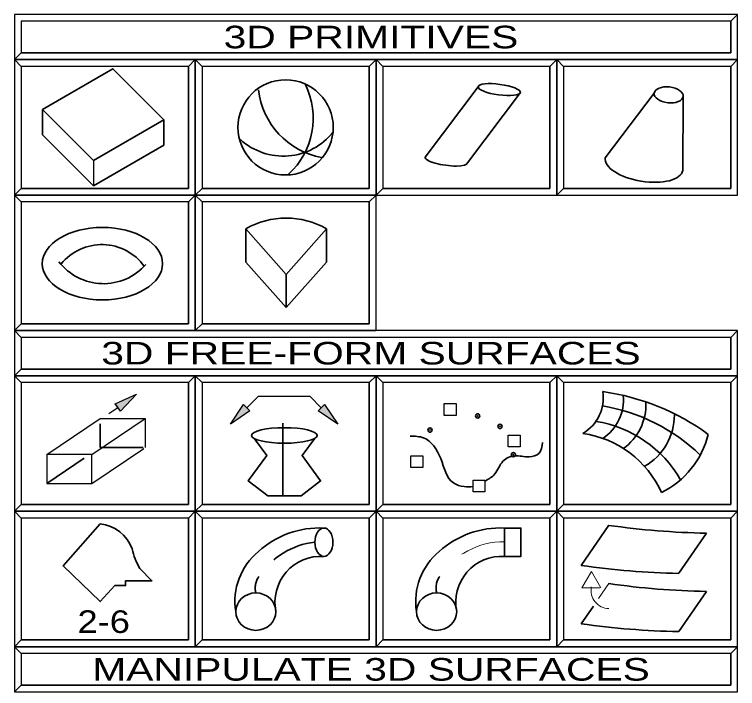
# Model space of a CAD drawing. Extents: x 95906.9 to 95918.9, y 90964.8 to 90972.9.
# Drawn here: x 95914.53 to 95916.13, y 90968.169 to 90969.662 of the extents above; entities that cross this region are included whole.
import ezdxf
from ezdxf.enums import TextEntityAlignment as Align

# ---------------------------------------------------------------- set-up
doc = ezdxf.new("R2010")
doc.units = 0
doc.header["$LTSCALE"] = 0.019
doc.header["$PDMODE"] = 32
doc.header["$PDSIZE"] = 0.0095
doc.linetypes.add('MEDIUM_DASHED', pattern=[4.5, 3, -1.5])
for name, color, linetype, lineweight in [('1', 7, 'Continuous', 25), ('11', 7, 'Continuous', 25), ('17', 7, 'Continuous', 25), ('18', 7, 'Continuous', 25), ('2', 7, 'Continuous', 13), ('3', 7, 'Continuous', 25), ('4', 7, 'Continuous', 35), ('6', 7, 'Continuous', 35), ('7', 7, 'Continuous', 35)]:
    doc.layers.add(name, color=color, linetype=linetype, lineweight=lineweight)

msp = doc.modelspace()

# ---------------------------------------------------------------- hatches: boundary and pattern name
at = {"layer": '6'}
for points in [[(95914.7526, 90968.7998), (95914.8002, 90968.8212), (95914.7644, 90968.7832)], [(95915.0509, 90968.7838), (95915.0075, 90968.7548), (95915.0365, 90968.7982)], [(95915.216, 90968.7982), (95915.245, 90968.7548), (95915.2016, 90968.7838)]]:
    msp.add_hatch(color=256, dxfattribs=at).paths.add_polyline_path(points)

# ---------------------------------------------------------------- linework, layer by layer
at = {"layer": '1'}
for points in [[(95914.5298, 90969.5617), (95916.1298, 90969.5617), (95916.1298, 90969.6617), (95914.5298, 90969.6617)], [(95914.5298, 90969.2617), (95914.9298, 90969.2617), (95914.9298, 90969.5617), (95914.5298, 90969.5617)], [(95914.9298, 90969.2617), (95915.3298, 90969.2617), (95915.3298, 90969.5617), (95914.9298, 90969.5617)], [(95915.3298, 90969.2617), (95915.7298, 90969.2617), (95915.7298, 90969.5617), (95915.3298, 90969.5617)], [(95915.7298, 90969.2617), (95916.1298, 90969.2617), (95916.1298, 90969.5617), (95915.7298, 90969.5617)], [(95914.5298, 90968.9617), (95914.9298, 90968.9617), (95914.9298, 90969.2617), (95914.5298, 90969.2617)], [(95914.9298, 90968.9617), (95915.3298, 90968.9617), (95915.3298, 90969.2617), (95914.9298, 90969.2617)], [(95914.5298, 90968.8617), (95916.1298, 90968.8617), (95916.1298, 90968.9617), (95914.5298, 90968.9617)], [(95914.5298, 90968.5617), (95914.9298, 90968.5617), (95914.9298, 90968.8617), (95914.5298, 90968.8617)], [(95914.9298, 90968.5617), (95915.3298, 90968.5617), (95915.3298, 90968.8617), (95914.9298, 90968.8617)], [(95915.3298, 90968.5617), (95915.7298, 90968.5617), (95915.7298, 90968.8617), (95915.3298, 90968.8617)], [(95915.7298, 90968.5617), (95916.1298, 90968.5617), (95916.1298, 90968.8617), (95915.7298, 90968.8617)], [(95914.5298, 90968.2617), (95914.9298, 90968.2617), (95914.9298, 90968.5617), (95914.5298, 90968.5617)], [(95914.9298, 90968.2617), (95915.3298, 90968.2617), (95915.3298, 90968.5617), (95914.9298, 90968.5617)], [(95915.3298, 90968.2617), (95915.7298, 90968.2617), (95915.7298, 90968.5617), (95915.3298, 90968.5617)], [(95915.7298, 90968.2617), (95916.1298, 90968.2617), (95916.1298, 90968.5617), (95915.7298, 90968.5617)], [(95914.5298, 90968.1617), (95916.1298, 90968.1617), (95916.1298, 90968.2617), (95914.5298, 90968.2617)]]:
    msp.add_lwpolyline(points, close=True, dxfattribs=at)
at = {"layer": '11'}
for points in [[(95914.5448, 90969.2767), (95914.9148, 90969.2767), (95914.9148, 90969.5467), (95914.5448, 90969.5467)], [(95914.9448, 90969.2767), (95915.3148, 90969.2767), (95915.3148, 90969.5467), (95914.9448, 90969.5467)], [(95915.3448, 90969.2767), (95915.7148, 90969.2767), (95915.7148, 90969.5467), (95915.3448, 90969.5467)], [(95915.7448, 90969.2767), (95916.1148, 90969.2767), (95916.1148, 90969.5467), (95915.7448, 90969.5467)], [(95914.5448, 90968.9767), (95914.9148, 90968.9767), (95914.9148, 90969.2467), (95914.5448, 90969.2467)], [(95914.9448, 90968.9767), (95915.3148, 90968.9767), (95915.3148, 90969.2467), (95914.9448, 90969.2467)], [(95914.5448, 90968.5767), (95914.9148, 90968.5767), (95914.9148, 90968.8467), (95914.5448, 90968.8467)], [(95914.9448, 90968.5767), (95915.3148, 90968.5767), (95915.3148, 90968.8467), (95914.9448, 90968.8467)], [(95915.3448, 90968.5767), (95915.7148, 90968.5767), (95915.7148, 90968.8467), (95915.3448, 90968.8467)], [(95915.7448, 90968.5767), (95916.1148, 90968.5767), (95916.1148, 90968.8467), (95915.7448, 90968.8467)], [(95914.5448, 90968.2767), (95914.9148, 90968.2767), (95914.9148, 90968.5467), (95914.5448, 90968.5467)], [(95914.9448, 90968.2767), (95915.3148, 90968.2767), (95915.3148, 90968.5467), (95914.9448, 90968.5467)], [(95915.3448, 90968.2767), (95915.7148, 90968.2767), (95915.7148, 90968.5467), (95915.3448, 90968.5467)], [(95915.7448, 90968.2767), (95916.1148, 90968.2767), (95916.1148, 90968.5467), (95915.7448, 90968.5467)]]:
    msp.add_lwpolyline(points, close=True, dxfattribs=at)
at = {"layer": '17'}
for points in [[(95914.5448, 90969.5767), (95916.1148, 90969.5767), (95916.1148, 90969.6467), (95914.5448, 90969.6467)], [(95914.5448, 90968.8767), (95916.1148, 90968.8767), (95916.1148, 90968.9467), (95914.5448, 90968.9467)]]:
    msp.add_lwpolyline(points, close=True, dxfattribs=at)
at = {"layer": '18'}
msp.add_lwpolyline([(95914.5448, 90968.1767), (95916.1148, 90968.1767), (95916.1148, 90968.2467), (95914.5448, 90968.2467)], close=True, dxfattribs=at)
at = {"layer": '2'}
for points in [[(95914.5298, 90969.6617), (95914.5298, 90969.5617), (95914.5448, 90969.5767), (95914.5448, 90969.6467), (95916.1148, 90969.6467), (95916.1298, 90969.6617)], [(95914.5298, 90969.5617), (95914.5298, 90969.2617), (95914.5448, 90969.2767), (95914.5448, 90969.5467), (95914.9148, 90969.5467), (95914.9298, 90969.5617)], [(95914.9298, 90969.5617), (95914.9298, 90969.2617), (95914.9448, 90969.2767), (95914.9448, 90969.5467), (95915.3148, 90969.5467), (95915.3298, 90969.5617)], [(95915.3298, 90969.5617), (95915.3298, 90969.2617), (95915.3448, 90969.2767), (95915.3448, 90969.5467), (95915.7148, 90969.5467), (95915.7298, 90969.5617)], [(95915.7298, 90969.5617), (95915.7298, 90969.2617), (95915.7448, 90969.2767), (95915.7448, 90969.5467), (95916.1148, 90969.5467), (95916.1298, 90969.5617)], [(95914.5298, 90969.2617), (95914.5298, 90968.9617), (95914.5448, 90968.9767), (95914.5448, 90969.2467), (95914.9148, 90969.2467), (95914.9298, 90969.2617)], [(95914.9298, 90969.2617), (95914.9298, 90968.9617), (95914.9448, 90968.9767), (95914.9448, 90969.2467), (95915.3148, 90969.2467), (95915.3298, 90969.2617)], [(95914.5298, 90968.9617), (95914.5298, 90968.8617), (95914.5448, 90968.8767), (95914.5448, 90968.9467), (95916.1148, 90968.9467), (95916.1298, 90968.9617)], [(95914.5298, 90968.8617), (95914.5298, 90968.5617), (95914.5448, 90968.5767), (95914.5448, 90968.8467), (95914.9148, 90968.8467), (95914.9298, 90968.8617)], [(95914.9298, 90968.8617), (95914.9298, 90968.5617), (95914.9448, 90968.5767), (95914.9448, 90968.8467), (95915.3148, 90968.8467), (95915.3298, 90968.8617)], [(95915.3298, 90968.8617), (95915.3298, 90968.5617), (95915.3448, 90968.5767), (95915.3448, 90968.8467), (95915.7148, 90968.8467), (95915.7298, 90968.8617)], [(95915.7298, 90968.8617), (95915.7298, 90968.5617), (95915.7448, 90968.5767), (95915.7448, 90968.8467), (95916.1148, 90968.8467), (95916.1298, 90968.8617)], [(95914.5298, 90968.5617), (95914.5298, 90968.2617), (95914.5448, 90968.2767), (95914.5448, 90968.5467), (95914.9148, 90968.5467), (95914.9298, 90968.5617)], [(95914.9298, 90968.5617), (95914.9298, 90968.2617), (95914.9448, 90968.2767), (95914.9448, 90968.5467), (95915.3148, 90968.5467), (95915.3298, 90968.5617)], [(95915.3298, 90968.5617), (95915.3298, 90968.2617), (95915.3448, 90968.2767), (95915.3448, 90968.5467), (95915.7148, 90968.5467), (95915.7298, 90968.5617)], [(95915.7298, 90968.5617), (95915.7298, 90968.2617), (95915.7448, 90968.2767), (95915.7448, 90968.5467), (95916.1148, 90968.5467), (95916.1298, 90968.5617)], [(95914.5298, 90968.2617), (95914.5298, 90968.1617), (95914.5448, 90968.1767), (95914.5448, 90968.2467), (95916.1148, 90968.2467), (95916.1298, 90968.2617)]]:
    msp.add_lwpolyline(points, close=True, dxfattribs=at)
at = {"layer": '3'}
for points in [[(95914.5298, 90969.5617), (95916.1298, 90969.5617), (95916.1298, 90969.6617), (95916.1148, 90969.6467), (95916.1148, 90969.5767), (95914.5448, 90969.5767)], [(95914.5298, 90969.2617), (95914.9298, 90969.2617), (95914.9298, 90969.5617), (95914.9148, 90969.5467), (95914.9148, 90969.2767), (95914.5448, 90969.2767)], [(95914.9298, 90969.2617), (95915.3298, 90969.2617), (95915.3298, 90969.5617), (95915.3148, 90969.5467), (95915.3148, 90969.2767), (95914.9448, 90969.2767)], [(95915.3298, 90969.2617), (95915.7298, 90969.2617), (95915.7298, 90969.5617), (95915.7148, 90969.5467), (95915.7148, 90969.2767), (95915.3448, 90969.2767)], [(95915.7298, 90969.2617), (95916.1298, 90969.2617), (95916.1298, 90969.5617), (95916.1148, 90969.5467), (95916.1148, 90969.2767), (95915.7448, 90969.2767)], [(95914.5298, 90968.9617), (95914.9298, 90968.9617), (95914.9298, 90969.2617), (95914.9148, 90969.2467), (95914.9148, 90968.9767), (95914.5448, 90968.9767)], [(95914.9298, 90968.9617), (95915.3298, 90968.9617), (95915.3298, 90969.2617), (95915.3148, 90969.2467), (95915.3148, 90968.9767), (95914.9448, 90968.9767)], [(95914.5298, 90968.8617), (95916.1298, 90968.8617), (95916.1298, 90968.9617), (95916.1148, 90968.9467), (95916.1148, 90968.8767), (95914.5448, 90968.8767)], [(95914.5298, 90968.5617), (95914.9298, 90968.5617), (95914.9298, 90968.8617), (95914.9148, 90968.8467), (95914.9148, 90968.5767), (95914.5448, 90968.5767)], [(95914.9298, 90968.5617), (95915.3298, 90968.5617), (95915.3298, 90968.8617), (95915.3148, 90968.8467), (95915.3148, 90968.5767), (95914.9448, 90968.5767)], [(95915.3298, 90968.5617), (95915.7298, 90968.5617), (95915.7298, 90968.8617), (95915.7148, 90968.8467), (95915.7148, 90968.5767), (95915.3448, 90968.5767)], [(95915.7298, 90968.5617), (95916.1298, 90968.5617), (95916.1298, 90968.8617), (95916.1148, 90968.8467), (95916.1148, 90968.5767), (95915.7448, 90968.5767)], [(95914.5298, 90968.2617), (95914.9298, 90968.2617), (95914.9298, 90968.5617), (95914.9148, 90968.5467), (95914.9148, 90968.2767), (95914.5448, 90968.2767)], [(95914.9298, 90968.2617), (95915.3298, 90968.2617), (95915.3298, 90968.5617), (95915.3148, 90968.5467), (95915.3148, 90968.2767), (95914.9448, 90968.2767)], [(95915.3298, 90968.2617), (95915.7298, 90968.2617), (95915.7298, 90968.5617), (95915.7148, 90968.5467), (95915.7148, 90968.2767), (95915.3448, 90968.2767)], [(95915.7298, 90968.2617), (95916.1298, 90968.2617), (95916.1298, 90968.5617), (95916.1148, 90968.5467), (95916.1148, 90968.2767), (95915.7448, 90968.2767)], [(95914.5298, 90968.1617), (95916.1298, 90968.1617), (95916.1298, 90968.2617), (95916.1148, 90968.2467), (95916.1148, 90968.1767), (95914.5448, 90968.1767)]]:
    msp.add_lwpolyline(points, close=True, dxfattribs=at)
at = {"layer": '4'}
for p, q in [((95914.5448, 90969.5467), (95914.5298, 90969.5617)), ((95914.9448, 90969.5467), (95914.9298, 90969.5617)), ((95915.3448, 90969.5467), (95915.3298, 90969.5617)), ((95915.7448, 90969.5467), (95915.7298, 90969.5617)), ((95914.5448, 90969.2467), (95914.5298, 90969.2617)), ((95914.9448, 90969.2467), (95914.9298, 90969.2617)), ((95914.5448, 90968.9467), (95914.5298, 90968.9617)), ((95914.5448, 90968.8467), (95914.5298, 90968.8617)), ((95914.9448, 90968.8467), (95914.9298, 90968.8617)), ((95915.3448, 90968.8467), (95915.3298, 90968.8617)), ((95915.7448, 90968.8467), (95915.7298, 90968.8617)), ((95914.5448, 90968.5467), (95914.5298, 90968.5617)), ((95914.9448, 90968.5467), (95914.9298, 90968.5617)), ((95915.3448, 90968.5467), (95915.3298, 90968.5617)), ((95915.7448, 90968.5467), (95915.7298, 90968.5617)), ((95914.5448, 90968.2467), (95914.5298, 90968.2617))]:
    msp.add_line(p, q, dxfattribs=at)
at = {"layer": '6'}
for p, q in [((95915.5558, 90969.5016), (95915.4387, 90969.3456)), ((95915.5323, 90969.3331), (95915.6494, 90969.4891)), ((95915.9453, 90969.4873), (95915.8371, 90969.3446)), ((95916.0096, 90969.48), (95916.0085, 90969.3164)), ((95914.5919, 90969.4516), (95914.7048, 90969.3387)), ((95914.5919, 90969.4516), (95914.5919, 90969.3953)), ((95914.7048, 90969.3387), (95914.8605, 90969.4286)), ((95914.7048, 90969.2824), (95914.5919, 90969.3953)), ((95914.7048, 90969.2824), (95914.8605, 90969.3723)), ((95915.1311, 90969.0863), (95915.0419, 90969.187)), ((95915.0419, 90969.1133), (95915.0419, 90969.187)), ((95915.2203, 90969.1133), (95915.2203, 90969.187)), ((95915.1311, 90969.0126), (95915.0419, 90969.1133)), ((95915.1311, 90969.0126), (95915.2203, 90969.1133)), ((95915.0687, 90968.816), (95915.0437, 90968.791)), ((95915.1838, 90968.816), (95915.2088, 90968.791)), ((95915.1235, 90968.7566), (95915.1235, 90968.5971)), ((95915.845, 90968.5306), (95915.784, 90968.4417)), ((95916.0608, 90968.5131), (95915.9998, 90968.4243)), ((95916.0608, 90968.3842), (95915.9998, 90968.2953)), ((95915.811, 90968.3518), (95915.784, 90968.3128))]:
    msp.add_line(p, q, dxfattribs=at)
at = {"layer": '6', "lineweight": 25}
for p, q in [((95914.7048, 90969.3387), (95914.7048, 90969.2824)), ((95915.1838, 90968.816), (95915.0687, 90968.816)), ((95914.7641, 90968.7834), (95914.7524, 90968.8001)), ((95914.7389, 90968.7782), (95914.7582, 90968.7918)), ((95914.6013, 90968.6877), (95914.7192, 90968.7672)), ((95914.7007, 90968.6877), (95914.8187, 90968.7673)), ((95914.7007, 90968.6233), (95914.8158, 90968.7009))]:
    msp.add_line(p, q, dxfattribs=at)
at = {"layer": '6', "linetype": 'MEDIUM_DASHED'}
msp.add_line((95914.6013, 90968.6233), (95914.6901, 90968.6832), dxfattribs=at)
at = {"layer": '6', "lineweight": 13}
for p, q in [((95915.6145, 90968.4618), (95915.6505, 90968.4618)), ((95915.845, 90968.4015), (95915.8224, 90968.3687)), ((95915.7854, 90968.3924), (95915.825, 90968.3924))]:
    msp.add_line(p, q, dxfattribs=at)
at = {"layer": '6'}
for points in [[(95914.5919, 90969.4516), (95914.7476, 90969.5415), (95914.8605, 90969.4286), (95914.8605, 90969.3723)], [(95915.1311, 90969.0126), (95915.1311, 90969.0863), (95915.2203, 90969.187)], [(95915.0609, 90968.7224), (95915.0882, 90968.6853), (95915.0473, 90968.6288), (95915.0902, 90968.5956), (95915.1644, 90968.5956)], [(95915.1937, 90968.7224), (95915.1664, 90968.6853), (95915.2073, 90968.6288), (95915.1644, 90968.5956)], [(95914.7195, 90968.5336), (95914.6379, 90968.4409), (95914.7195, 90968.3616), (95914.7516, 90968.397), (95914.7756, 90968.397), (95914.7756, 90968.4079), (95914.8341, 90968.4079), (95914.8073, 90968.4348)]]:
    msp.add_lwpolyline(points, dxfattribs=at)
at = {"layer": '6', "lineweight": 25}
for points in [[(95914.7526, 90968.7998), (95914.8002, 90968.8212), (95914.7644, 90968.7832)], [(95915.481, 90968.8), (95915.507, 90968.8), (95915.507, 90968.774), (95915.481, 90968.774)], [(95915.0509, 90968.7838), (95915.0075, 90968.7548), (95915.0365, 90968.7982)], [(95915.216, 90968.7982), (95915.245, 90968.7548), (95915.2016, 90968.7838)], [(95915.6226, 90968.7302), (95915.6486, 90968.7302), (95915.6486, 90968.7042), (95915.6226, 90968.7042)], [(95914.6013, 90968.6233), (95914.7007, 90968.6233), (95914.7007, 90968.6877), (95914.6013, 90968.6877)], [(95915.4071, 90968.6843), (95915.4331, 90968.6843), (95915.4331, 90968.6583), (95915.4071, 90968.6583)], [(95915.5448, 90968.6304), (95915.5708, 90968.6304), (95915.5708, 90968.6044), (95915.5448, 90968.6044)]]:
    msp.add_lwpolyline(points, close=True, dxfattribs=at)
msp.add_lwpolyline([(95914.7192, 90968.7672), (95914.8187, 90968.7672), (95914.8187, 90968.7028), (95914.8187, 90968.7028)], dxfattribs=at)
at = {"layer": '6', "linetype": 'MEDIUM_DASHED'}
msp.add_lwpolyline([(95914.7192, 90968.755), (95914.7192, 90968.7028), (95914.8145, 90968.7028)], dxfattribs=at)
at = {"layer": '6'}
msp.add_lwpolyline([(95915.6145, 90968.5245), (95915.6505, 90968.5245), (95915.6505, 90968.4618), (95915.6145, 90968.4618)], close=True, dxfattribs=at)
at = {"layer": '6', "lineweight": 13}
msp.add_lwpolyline([(95915.8271, 90968.3924), (95915.8063, 90968.4284), (95915.7854, 90968.3924)], dxfattribs=at)
at = {"layer": '6'}
msp.add_circle((95915.1298, 90969.4117), 0.1054, dxfattribs=at)
for centre, radius, start, end in [((95915.0213, 90969.4321), 0.1694, 312.7535, 26.049), ((95915.2416, 90969.5151), 0.1732, 186.6935, 259.2749), ((95915.1245, 90969.4894), 0.1413, 227.8876, 321.4178), ((95915.1311, 90969.0325), 0.1784, 60, 119.9969), ((95914.7231, 90969.0361), 0.116, 36.0967, 140.8474), ((95914.7268, 90969.1897), 0.1241, 217.4186, 318.9458), ((95915.741, 90968.813), 0.0917, 300.3182, 8.4963), ((95915.7581, 90968.3096), 0.5222, 53.9871, 81.8992), ((95915.7728, 90968.8089), 0.1045, 304.4958, 4.9818), ((95915.8076, 90968.7977), 0.1195, 305.5164, 2.2558), ((95915.7654, 90968.3941), 0.4061, 46.01, 80.722), ((95915.8589, 90968.7751), 0.1311, 299.912, 0.1769), ((95915.7746, 90968.4997), 0.2644, 29.8659, 80.8902), ((95915.7562, 90968.5108), 0.2252, 24.1763, 82.0604), ((95915.8735, 90968.7798), 0.1975, 296.4877, 345.9828), ((95914.7109, 90968.4495), 0.0845, 20.2056, 84.1342), ((95916.0925, 90970.2554), 1.7425, 261.8343, 268.9564), ((95915.2046, 90968.3244), 0.2003, 87.1764, 132.3766), ((95915.6046, 90968.3244), 0.2003, 87.1764, 132.3766), ((95914.9382, 90968.5111), 0.1515, 192.3341, 210.2299), ((95915.1613, 90968.3618), 0.1437, 129.6749, 188.9392), ((95915.5613, 90968.3618), 0.1437, 129.6749, 188.9392), ((95915.2081, 90968.3601), 0.1019, 86.3899, 191.6709), ((95915.6081, 90968.3601), 0.1019, 86.3899, 191.6709), ((95916.0315, 90970.1665), 1.7425, 261.8343, 268.9564), ((95916.0925, 90970.1264), 1.7425, 261.8343, 268.9564), ((95916.0315, 90970.0375), 1.7425, 261.8343, 268.9564)]:
    msp.add_arc(centre, radius, start, end, dxfattribs=at)
at = {"layer": '6', "linetype": 'MEDIUM_DASHED'}
for centre, radius, start, end in [((95915.2134, 90968.3236), 0.1707, 96.3612, 146.6103), ((95915.1071, 90968.3916), 0.0445, 144.4452, 193.8419), ((95915.5071, 90968.3916), 0.0445, 144.4452, 193.8419)]:
    msp.add_arc(centre, radius, start, end, dxfattribs=at)
at = {"layer": '6', "linetype": 'MEDIUM_DASHED', "lineweight": 13}
msp.add_arc((95915.6134, 90968.3236), 0.1707, 89.6345, 146.6103, dxfattribs=at)
at = {"layer": '6', "lineweight": 13}
msp.add_arc((95915.8461, 90968.3867), 0.0405, 169.5588, 268.6398, dxfattribs=at)
at = {"layer": '6'}
for centre, major_axis, ratio in [((95915.6026, 90969.4953), (0.0468, -0.0063), 0.248221), ((95915.9774, 90969.4836), (-0.032, 0.0037), 0.546725), ((95914.7245, 90969.1099), (0.1331, 0), 0.603138), ((95915.1271, 90968.7296), (-0.0726, 0), 0.237033), ((95915.2145, 90968.4932), (0, 0.0314), 0.636715), ((95915.0639, 90968.3395), (0.0444, 0), 0.93307), ((95915.4639, 90968.3395), (0.0444, 0), 0.93307)]:
    msp.add_ellipse(centre, major_axis=major_axis, ratio=ratio, dxfattribs=at)
for centre, major_axis, ratio, start_param, end_param in [((95915.4855, 90969.3393), (0.0468, -0.0063), 0.248221, 3.144072, 6.285708), ((95915.9228, 90969.3305), (0.0857, -0.0141), 0.443071, 3.141508, 6.282887)]:
    msp.add_ellipse(centre, major_axis=major_axis, ratio=ratio, start_param=start_param, end_param=end_param, dxfattribs=at)
for points in [[(95915.4052, 90968.7281), (95915.4351, 90968.7242), (95915.473, 90968.6783), (95915.501, 90968.6244), (95915.5249, 90968.6164), (95915.5449, 90968.6164)], [(95915.5708, 90968.6284), (95915.5928, 90968.6443), (95915.6107, 90968.6723), (95915.6366, 90968.6843), (95915.6686, 90968.6823), (95915.6905, 90968.6902), (95915.6985, 90968.7142)]]:
    msp.add_spline(points, degree=3, dxfattribs=at)
for p in [(95915.5548, 90968.7727), (95915.6042, 90968.7496), (95915.4493, 90968.7414), (95915.6339, 90968.687)]:
    msp.add_point(p, dxfattribs=at)

# ---------------------------------------------------------------- texts
at = {"layer": '6', "width": 1.2}
msp.add_text('2-6', height=0.05, dxfattribs=at).set_placement((95914.6693, 90968.2923))
at = {"layer": '7', "width": 1.35}
for s, p in [('3D PRIMITIVES', (95915.3187, 90969.5867)), ('3D FREE-FORM SURFACES', (95915.3187, 90968.8867)), ('MANIPULATE 3D SURFACES', (95915.3188, 90968.1867))]:
    msp.add_text(s, height=0.05, dxfattribs=at).set_placement(p, align=Align.CENTER)

doc.saveas('drawing.dxf')
